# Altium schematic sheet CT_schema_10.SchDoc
size 390 x 278 mm
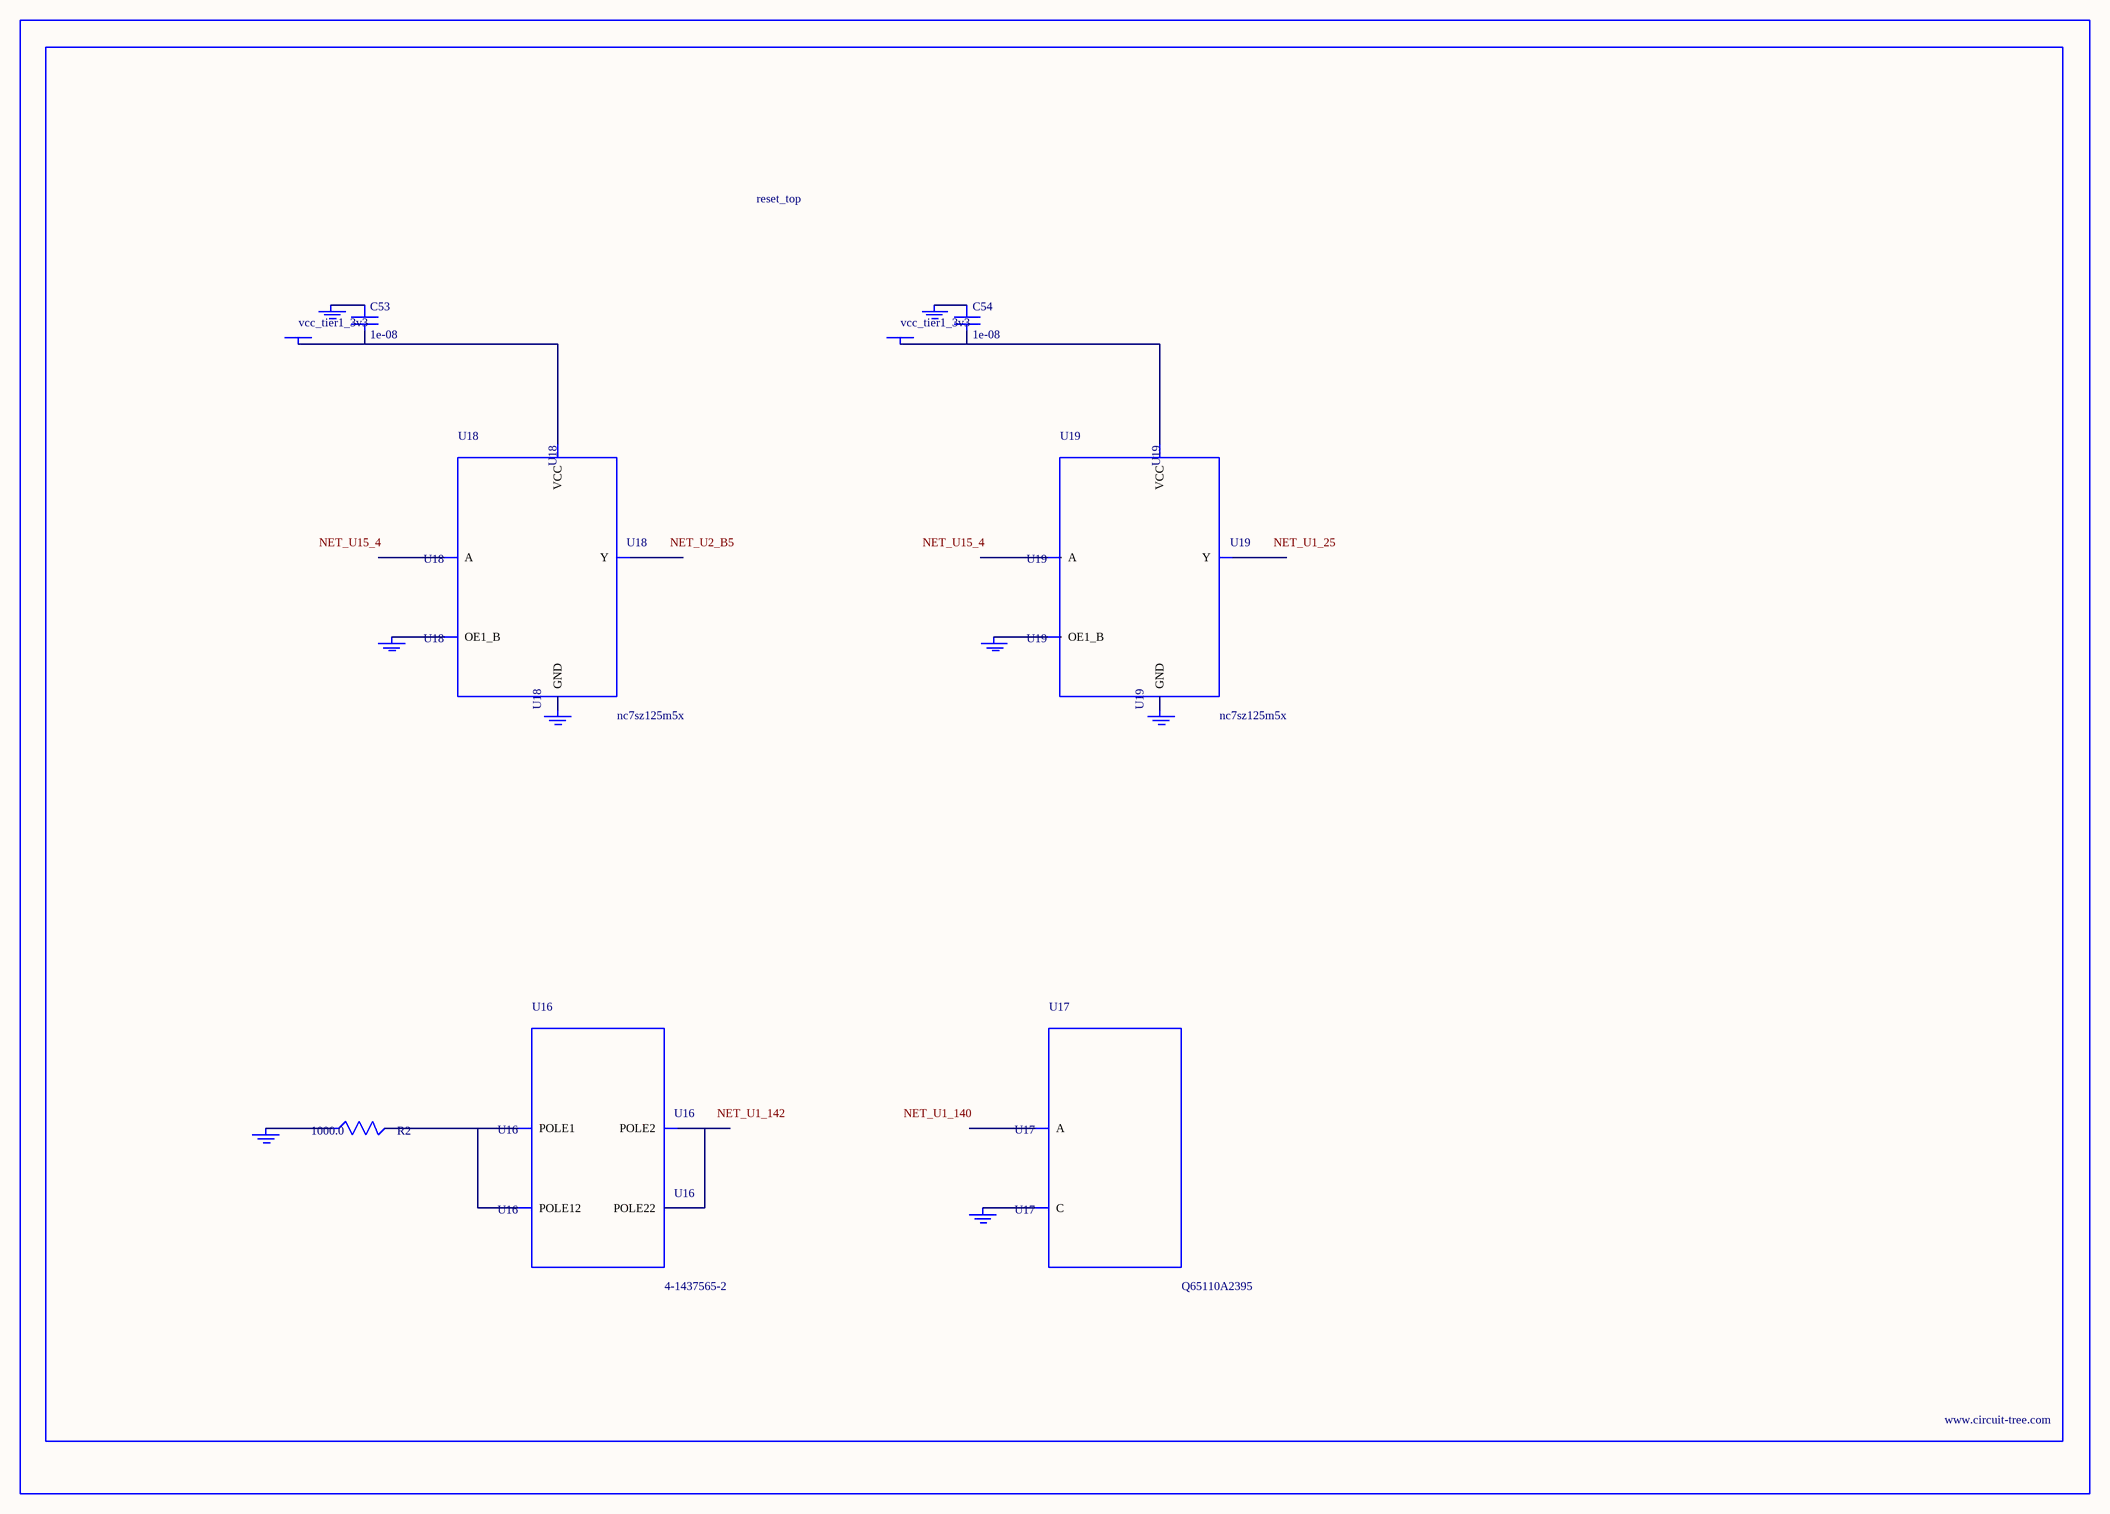
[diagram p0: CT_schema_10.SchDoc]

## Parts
BORDER9  (no value)
C53  1e-08  [C0402]
C54  1e-08  [C0402]
GND_INSTANCE_9_0  (no value)
GND_INSTANCE_9_1  (no value)
GND_INSTANCE_9_2  (no value)
GND_INSTANCE_9_3  (no value)
GND_INSTANCE_9_4  (no value)
GND_INSTANCE_9_5  (no value)
GND_INSTANCE_9_6  (no value)
GND_INSTANCE_9_7  (no value)
POWER_INSTANCE_9_0  vcc_tier1_3v3
POWER_INSTANCE_9_1  vcc_tier1_3v3
R2  1000.0  [R0603]
U16  4-1437565-2  [SW_4-1437565-2]
U17  Q65110A2395  [LGM67K-G1J2-24-Z]
U18  nc7sz125m5x  [NC7SZ125M5X]
U19  nc7sz125m5x  [NC7SZ125M5X]

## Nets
NetC53_1: C53.1 GND_INSTANCE_9_2.0(GND)
NetC53_2: C53.2 POWER_INSTANCE_9_0.0(PWR) U18.5(VCC)
NetC54_1: C54.1 GND_INSTANCE_9_5.0(GND)
NetC54_2: C54.2 POWER_INSTANCE_9_1.0(PWR) U19.5(VCC)
NetGND_INSTANCE_9_0_0: GND_INSTANCE_9_0.0(GND) R2.1
NetGND_INSTANCE_9_1_0: GND_INSTANCE_9_1.0(GND) U17.C
NetGND_INSTANCE_9_3_0: GND_INSTANCE_9_3.0(GND) U18.1(OE1_B)
NetGND_INSTANCE_9_4_0: GND_INSTANCE_9_4.0(GND) U18.3(GND)
NetGND_INSTANCE_9_6_0: GND_INSTANCE_9_6.0(GND) U19.1(OE1_B)
NetGND_INSTANCE_9_7_0: GND_INSTANCE_9_7.0(GND) U19.3(GND)
NetR2_2: R2.2 U16.1(POLE1) U16.2(POLE12)
NetU16_3: U16.3(POLE2) U16.4(POLE22)

Not connected (* = marked no-connect by the designer): U17 A; U18 2(A) 4(Y); U19 2(A) 4(Y)

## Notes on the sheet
- Labels drawn without touching a wire or pin: NET_U1_25, NET_U1_140, NET_U1_142, NET_U2_B5, NET_U15_4

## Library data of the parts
BORDER9 = BORDER_PAGE9
C53 C54 = C0402C103K3RAC
GND_INSTANCE_9_0-GND_INSTANCE_9_7 = GND
POWER_INSTANCE_9_0 POWER_INSTANCE_9_1 = PWR
R2 = RC0603JR-071KL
